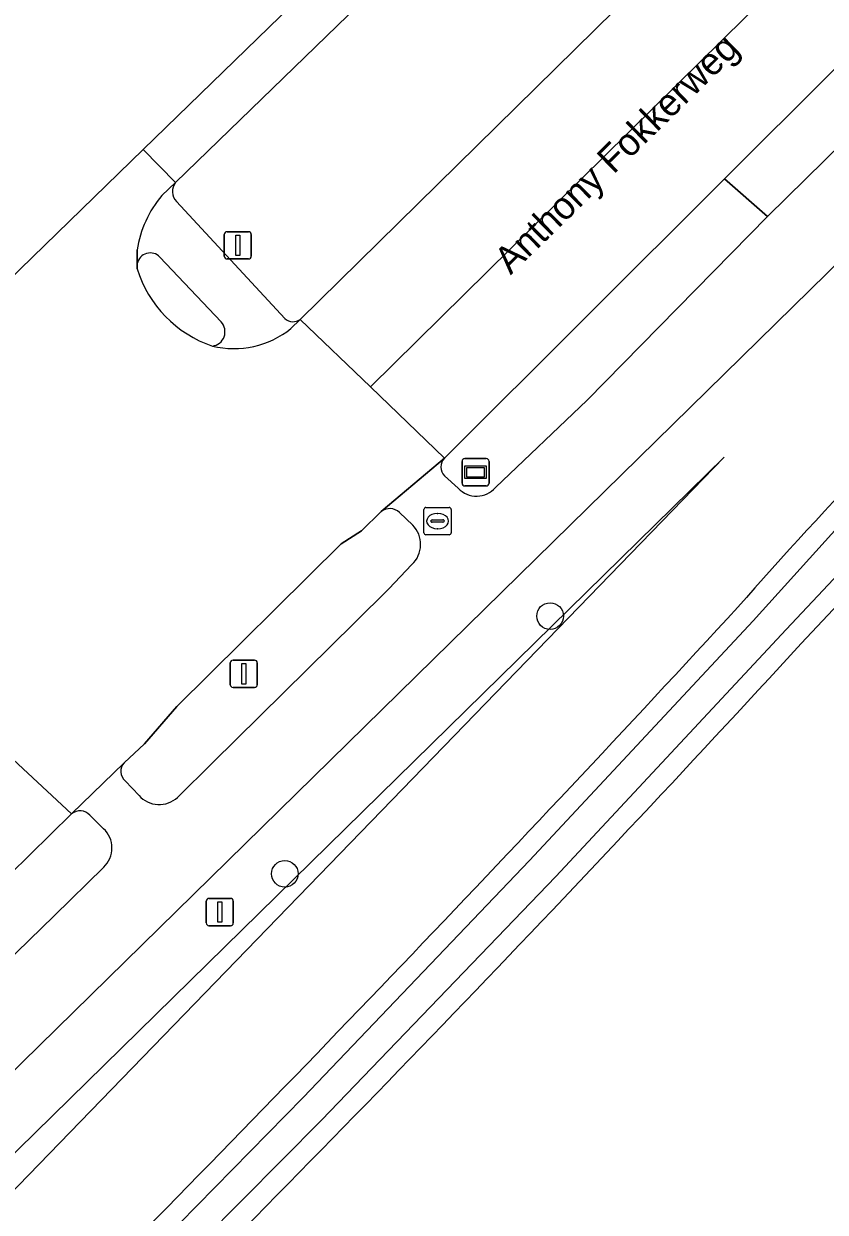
# Model space of a CAD drawing. Extents: x 156502 to 159075, y 384229 to 386100.
# Drawn here: x 156889.57 to 156918.98, y 385882.89 to 385926.49 of the extents above; entities that cross this region are included whole.
import ezdxf

# ---------------------------------------------------------------- set-up
doc = ezdxf.new("R2010")
doc.units = 0
for name, color, linetype in [('IMGEO_Berm_groen', 7, 'Continuous'), ('IMGEO_Boom', 7, 'Continuous'), ('IMGEO_Brandkraan', 7, 'Continuous'), ('IMGEO_Fietspad_gesloten', 7, 'Continuous'), ('IMGEO_Fietspad_open', 7, 'Continuous'), ('IMGEO_Groenvoorziening', 7, 'Continuous'), ('IMGEO_Lichtmast', 7, 'Continuous'), ('IMGEO_Loofbos', 7, 'Continuous'), ('IMGEO_Oever', 7, 'Continuous'), ('IMGEO_Openbare_ruimte_label', 7, 'Continuous'), ('IMGEO_Rijbaan_regionaal_gesloten', 7, 'Continuous'), ('IMGEO_Verkeersbordpaal', 7, 'Continuous'), ('IMGEO_Verkeerseiland_groen', 7, 'Continuous'), ('IMGEO_Verkeerseiland_open', 7, 'Continuous'), ('IMGEO_Verklikker', 7, 'Continuous'), ('IMGEO_Waterloop', 7, 'Continuous')]:
    doc.layers.add(name, color=color, linetype=linetype)

msp = doc.modelspace()

# ---------------------------------------------------------------- linework, layer by layer
at = {"layer": 'IMGEO_Berm_groen'}
msp.add_lwpolyline([(156943.436, 385945.532), (156945.978, 385947.733), (156944.931, 385949.532), (156941.12, 385946.235), (156931.18, 385936.654), (156915.286, 385920.806), (156916.861, 385919.427)], close=True, dxfattribs=at)
for points in [[(156916.861, 385919.427), (156915.286, 385920.806), (156905.009, 385910.559)], [(156906.88, 385909.479), (156910.242, 385912.682), (156916.861, 385919.427)], [(156905.007, 385909.901), (156905.515, 385909.453)], [(156891.327, 385897.504), (156890.556, 385896.744), (156880.841, 385887.205), (156882.39, 385885.7), (156890.686, 385893.756)], [(156892.499, 385896.958), (156891.994, 385897.455)], [(156890.686, 385893.756), (156892.502, 385895.546)]]:
    msp.add_lwpolyline(points, dxfattribs=at)
for centre, radius, start, end in [((156905.345, 385910.229), 0.471, 135.5045, 224.1472), ((156906.186, 385910.074), 0.914, 222.7938, 319.3887), ((156891.636, 385897.14), 0.477, 41.2701, 130.3268), ((156891.834, 385896.251), 0.971, 313.4602, 46.7832)]:
    msp.add_arc(centre, radius, start, end, dxfattribs=at)
at = {"layer": 'IMGEO_Boom'}
for centre in [(156908.883, 385904.761), (156899.148, 385895.304)]:
    msp.add_circle(centre, 0.489, dxfattribs=at)
at = {"layer": 'IMGEO_Brandkraan'}
for p, q in [((156904.254, 385907.821), (156904.254, 385908.673)), ((156904.329, 385908.747), (156905.181, 385908.747)), ((156904.742, 385908.527), (156904.767, 385908.527)), ((156905.255, 385908.673), (156905.255, 385907.821)), ((156904.513, 385908.241), (156904.513, 385908.253)), ((156904.951, 385908.204), (156904.553, 385908.204)), ((156904.556, 385908.29), (156904.954, 385908.29)), ((156904.765, 385907.967), (156904.74, 385907.967)), ((156904.997, 385908.253), (156904.997, 385908.241)), ((156905.181, 385907.747), (156904.329, 385907.747))]:
    msp.add_line(p, q, dxfattribs=at)
for points in [[(156904.254, 385907.821), (156904.254, 385908.673)], [(156904.329, 385908.747), (156905.181, 385908.747)], [(156905.255, 385908.673), (156905.255, 385907.821)], [(156905.181, 385907.747), (156904.329, 385907.747)]]:
    msp.add_lwpolyline(points, dxfattribs=at)
for centre, radius, start, end in [((156904.331, 385908.671), 0.0765, 91.552, 178.448), ((156904.331, 385908.671), 0.0765, 91.552, 178.448), ((156905.179, 385908.671), 0.0765, 1.552, 88.448), ((156905.179, 385908.671), 0.0765, 1.552, 88.448), ((156904.553, 385908.25), 0.0403, 85.8775, 175.7526), ((156904.55, 385908.24), 0.0366, 178.938, 274.7102), ((156904.954, 385908.247), 0.043, 264.8664, 352.4533), ((156904.958, 385908.252), 0.0386, 1.7309, 96.639), ((156904.331, 385907.823), 0.0765, 181.552, 268.448), ((156904.331, 385907.823), 0.0765, 181.552, 268.448), ((156905.179, 385907.823), 0.0765, 271.552, 358.448), ((156905.179, 385907.823), 0.0765, 271.552, 358.448)]:
    msp.add_arc(centre, radius, start, end, dxfattribs=at)
for centre, major_axis, ratio, start_param, end_param in [((156904.741, 385908.247), (-0.387, 0.002), 0.722429, 4.712389, 7.853982), ((156904.766, 385908.247), (-0.39, 0.002), 0.717154, 1.570796, 4.712389)]:
    msp.add_ellipse(centre, major_axis=major_axis, ratio=ratio, start_param=start_param, end_param=end_param, dxfattribs=at)
at = {"layer": 'IMGEO_Fietspad_gesloten'}
for points in [[(156873.791, 385872.985), (156944.187, 385942.001), (156947.572, 385944.991), (156947.985, 385945.377), (156946.393, 385948.094), (156945.978, 385947.733), (156943.436, 385945.532), (156916.861, 385919.427), (156910.242, 385912.682), (156906.88, 385909.479)], [(156905.009, 385910.559), (156902.688, 385908.6)], [(156905.515, 385909.453), (156905.007, 385909.901)], [(156903.357, 385908.566), (156903.843, 385908.097)], [(156903.815, 385906.653), (156902.968, 385905.759), (156901.719, 385904.522), (156896.499, 385899.38), (156895.214, 385898.109)], [(156893.251, 385899.377), (156891.327, 385897.504)], [(156893.799, 385898.18), (156893.291, 385898.71)], [(156891.994, 385897.455), (156892.499, 385896.958)], [(156892.502, 385895.546), (156890.686, 385893.756), (156882.39, 385885.7), (156878.321, 385881.75)]]:
    msp.add_lwpolyline(points, dxfattribs=at)
for centre, radius, start, end in [((156905.345, 385910.229), 0.471, 135.5045, 224.1472), ((156906.186, 385910.074), 0.914, 222.7938, 319.3887), ((156903.002, 385908.185), 0.52, 47.025, 127.1562), ((156903.124, 385907.389), 1.01, 313.2216, 44.5567), ((156893.595, 385899.063), 0.466, 137.595, 229.2689), ((156894.541, 385898.827), 0.984, 221.0993, 313.1557), ((156891.636, 385897.14), 0.477, 41.2701, 130.3268), ((156891.834, 385896.251), 0.971, 313.4602, 46.7832)]:
    msp.add_arc(centre, radius, start, end, dxfattribs=at)
at = {"layer": 'IMGEO_Fietspad_open'}
for points in [[(156895.139, 385920.67), (156894.641, 385920.187)], [(156899.156, 385915.676), (156895.173, 385919.975)], [(156893.736, 385918.196), (156893.734, 385917.699)], [(156894.565, 385917.933), (156896.811, 385915.552)], [(156899.374, 385915.313), (156899.709, 385915.643)]]:
    msp.add_lwpolyline(points, dxfattribs=at)
for centre, radius, start, end in [((156895.54, 385920.341), 0.518, 140.6271, 224.9744), ((156897.567, 385917.656), 3.869, 139.1392, 171.9728), ((156894.211, 385917.598), 0.488, 43.4644, 167.9888), ((156896.43, 385915.191), 0.525, 276.7087, 43.4086), ((156899.453, 385916.007), 0.445, 228.1121, 305.0578), ((156897.286, 385917.892), 3.318, 256.1428, 309.0031)]:
    msp.add_arc(centre, radius, start, end, dxfattribs=at)
at = {"layer": 'IMGEO_Groenvoorziening'}
msp.add_lwpolyline([(156845.546, 385840.494), (156871.07, 385864.986), (156915.271, 385910.594), (156887.455, 385883.327), (156885.077, 385880.811)], dxfattribs=at)
at = {"layer": 'IMGEO_Lichtmast'}
for p, q in [((156897.029, 385918.865), (156897.819, 385918.865)), ((156897.819, 385918.865), (156897.029, 385918.865)), ((156896.929, 385917.965), (156896.929, 385918.765)), ((156896.929, 385918.765), (156896.929, 385917.965)), ((156897.919, 385918.765), (156897.919, 385917.965)), ((156897.919, 385917.965), (156897.919, 385918.765)), ((156897.819, 385917.865), (156897.029, 385917.865)), ((156897.029, 385917.865), (156897.819, 385917.865)), ((156897.148, 385902.242), (156897.148, 385903.042)), ((156897.148, 385903.042), (156897.148, 385902.242)), ((156897.248, 385903.142), (156898.038, 385903.142)), ((156898.038, 385903.142), (156897.248, 385903.142)), ((156898.138, 385903.042), (156898.138, 385902.242)), ((156898.138, 385902.242), (156898.138, 385903.042)), ((156898.038, 385902.142), (156897.248, 385902.142)), ((156897.248, 385902.142), (156898.038, 385902.142))]:
    msp.add_line(p, q, dxfattribs=at)
for points in [[(156897.349, 385918.74), (156897.499, 385918.74), (156897.499, 385917.99), (156897.349, 385917.99), (156897.349, 385918.74)], [(156897.568, 385903.017), (156897.718, 385903.017), (156897.718, 385902.267), (156897.568, 385902.267), (156897.568, 385903.017)]]:
    msp.add_lwpolyline(points, dxfattribs=at)
for centre, start, end in [((156897.029, 385918.765), 90, 180), ((156897.029, 385918.765), 90, 180), ((156897.819, 385918.765), 0, 90), ((156897.819, 385918.765), 360, 90), ((156897.029, 385917.965), 180, 270), ((156897.029, 385917.965), 180, 270), ((156897.819, 385917.965), 270, 0), ((156897.819, 385917.965), 270, 0), ((156897.248, 385903.042), 90, 180), ((156897.248, 385903.042), 90, 180), ((156898.038, 385903.042), 0, 90), ((156898.038, 385903.042), 360, 90), ((156897.248, 385902.242), 180, 270), ((156897.248, 385902.242), 180, 270), ((156898.038, 385902.242), 270, 0), ((156898.038, 385902.242), 270, 0)]:
    msp.add_arc(centre, 0.1, start, end, dxfattribs=at)
at = {"layer": 'IMGEO_Loofbos'}
for points in [[(156939.905, 385930.087), (156949.647, 385941.356), (156947.572, 385944.991), (156944.187, 385942.001), (156873.791, 385872.985)], [(157027.141, 385797.89), (157015.854, 385829.061), (157010.805, 385836.629), (157000, 385855.161), (156976.182, 385896.012), (156952.047, 385938.123), (156945.972, 385932.521), (156939.53, 385926.107), (156933.24, 385919.544), (156932.218, 385920.282), (156927.135, 385915.226), (156928.076, 385914.361), (156918.102, 385903.758)], [(156885.077, 385880.811), (156887.455, 385883.327), (156915.271, 385910.594), (156871.07, 385864.986), (156845.546, 385840.494)]]:
    msp.add_lwpolyline(points, dxfattribs=at)
for centre, radius, start, end in [((157023.66, 385810.802), 143.279, 132.78404, 138.84683), ((156213.51, 386552.027), 954.833, 315.185311, 317.348363), ((156324.09, 386449.06), 806.353, 314.801867, 317.448151)]:
    msp.add_arc(centre, radius, start, end, dxfattribs=at)
at = {"layer": 'IMGEO_Oever'}
for points in [[(156918.102, 385903.758), (156928.076, 385914.361), (156927.135, 385915.226), (156926.339, 385915.957)], [(156927.002, 385914.322), (156917.548, 385904.272), (156909.091, 385895.2), (156900.494, 385886.259), (156891.761, 385877.452), (156868.007, 385854.16), (156858.229, 385844.972), (156848.315, 385835.931), (156838.268, 385827.039), (156835.089, 385824.285), (156831.899, 385821.544), (156828.697, 385818.817), (156821.36, 385812.649), (156813.965, 385806.55), (156806.514, 385800.519), (156797.646, 385793.521), (156788.691, 385786.634)], [(156791.706, 385789.946), (156801.678, 385797.68), (156811.506, 385805.594), (156821.188, 385813.688), (156830.418, 385821.329), (156839.492, 385829.155), (156848.406, 385837.163), (156857.206, 385845.158), (156865.872, 385853.299), (156874.402, 385861.582), (156891.394, 385878.511), (156899.818, 385887.098), (156908.134, 385895.789), (156916.339, 385904.585), (156919.557, 385908.145)]]:
    msp.add_lwpolyline(points, dxfattribs=at)
for centre, radius, start, end in [((157023.66, 385810.802), 143.279, 132.78404, 138.84683), ((156213.51, 386552.027), 954.833, 315.185311, 317.348363), ((156324.09, 386449.06), 806.353, 314.801867, 317.448151)]:
    msp.add_arc(centre, radius, start, end, dxfattribs=at)
at = {"layer": 'IMGEO_Rijbaan_regionaal_gesloten'}
for points in [[(156893.955, 385921.876), (156895.139, 385920.67), (156906.616, 385931.802), (156937.548, 385961.776), (156938.067, 385962.314), (156937.167, 385963.852)], [(156943.271, 385953.427), (156943.141, 385953.648), (156941.394, 385956.632), (156941.305, 385956.548), (156941.217, 385956.463), (156911.246, 385926.983), (156899.709, 385915.643), (156902.29, 385913.167), (156922.067, 385932.665)], [(156931.18, 385936.654), (156933.089, 385939.03), (156944.958, 385950.544), (156943.271, 385953.427), (156922.067, 385932.665), (156902.29, 385913.167), (156905.009, 385910.559), (156915.286, 385920.806)]]:
    msp.add_lwpolyline(points, close=True, dxfattribs=at)
for points in [[(156894.641, 385920.187), (156895.139, 385920.67), (156893.955, 385921.876), (156879.95, 385908.272)], [(156893.733, 385917.499), (156893.734, 385917.699), (156893.736, 385918.196)], [(156883.686, 385904.586), (156886.34, 385902.126), (156888.823, 385899.825), (156891.327, 385897.504), (156893.251, 385899.377), (156894.006, 385900.067), (156895.189, 385901.448), (156901.217, 385907.408), (156901.965, 385907.883), (156902.688, 385908.6), (156905.009, 385910.559), (156902.29, 385913.167), (156899.709, 385915.643), (156899.374, 385915.313)], [(156795.342, 385814.425), (156799.114, 385817.224), (156814.798, 385828.866), (156818.543, 385831.737), (156834.72, 385845.107), (156844.675, 385853.743), (156855.634, 385863.406), (156880.278, 385886.652), (156880.841, 385887.205), (156890.556, 385896.744), (156891.327, 385897.504), (156888.823, 385899.825), (156879.362, 385890.785), (156870.119, 385881.999), (156843.887, 385857.992), (156834.982, 385850.173), (156825.856, 385842.577), (156813.575, 385832.664), (156801.037, 385822.91), (156788.389, 385813.487)]]:
    msp.add_lwpolyline(points, dxfattribs=at)
for centre, radius, start, end in [((156897.567, 385917.656), 3.869, 139.1392, 171.9728), ((156897.884, 385918.787), 4.346, 197.2394, 251.3045), ((156897.286, 385917.892), 3.318, 256.1428, 309.0031)]:
    msp.add_arc(centre, radius, start, end, dxfattribs=at)
at = {"layer": 'IMGEO_Verkeersbordpaal'}
for p, q in [((156896.266, 385893.5), (156896.266, 385894.3)), ((156896.266, 385894.3), (156896.266, 385893.5)), ((156896.366, 385894.4), (156897.156, 385894.4)), ((156897.156, 385894.4), (156896.366, 385894.4)), ((156897.256, 385894.3), (156897.256, 385893.5)), ((156897.256, 385893.5), (156897.256, 385894.3)), ((156897.156, 385893.4), (156896.366, 385893.4)), ((156896.366, 385893.4), (156897.156, 385893.4))]:
    msp.add_line(p, q, dxfattribs=at)
msp.add_lwpolyline([(156896.686, 385894.275), (156896.836, 385894.275), (156896.836, 385893.525), (156896.686, 385893.525), (156896.686, 385894.275)], dxfattribs=at)
for centre, start, end in [((156896.366, 385894.3), 90, 180), ((156896.366, 385894.3), 90, 180), ((156897.156, 385894.3), 0, 90), ((156897.156, 385894.3), 360, 90), ((156896.366, 385893.5), 180, 270), ((156896.366, 385893.5), 180, 270), ((156897.156, 385893.5), 270, 0), ((156897.156, 385893.5), 270, 0)]:
    msp.add_arc(centre, 0.1, start, end, dxfattribs=at)
at = {"layer": 'IMGEO_Verkeerseiland_groen'}
for points in [[(156902.688, 385908.6), (156901.965, 385907.883), (156901.217, 385907.408), (156895.189, 385901.448), (156894.006, 385900.067), (156893.251, 385899.377)], [(156903.843, 385908.097), (156903.357, 385908.566)], [(156901.719, 385904.522), (156902.968, 385905.759), (156903.815, 385906.653)], [(156895.214, 385898.109), (156896.499, 385899.38), (156901.719, 385904.522)], [(156893.291, 385898.71), (156893.799, 385898.18)]]:
    msp.add_lwpolyline(points, dxfattribs=at)
for centre, radius, start, end in [((156903.002, 385908.185), 0.52, 47.025, 127.1562), ((156903.124, 385907.389), 1.01, 313.2216, 44.5567), ((156893.595, 385899.063), 0.466, 137.595, 229.2689), ((156894.541, 385898.827), 0.984, 221.0993, 313.1557)]:
    msp.add_arc(centre, radius, start, end, dxfattribs=at)
at = {"layer": 'IMGEO_Verkeerseiland_open'}
for points in [[(156899.709, 385915.643), (156911.246, 385926.983), (156906.616, 385931.802), (156895.139, 385920.67)], [(156895.173, 385919.975), (156899.156, 385915.676)], [(156893.734, 385917.699), (156893.733, 385917.499)], [(156896.811, 385915.552), (156894.565, 385917.933)]]:
    msp.add_lwpolyline(points, dxfattribs=at)
for centre, radius, start, end in [((156895.54, 385920.341), 0.518, 140.6271, 224.9744), ((156894.211, 385917.598), 0.488, 43.4644, 167.9888), ((156897.884, 385918.787), 4.346, 197.2394, 251.3045), ((156896.43, 385915.191), 0.525, 276.7087, 43.4086), ((156899.453, 385916.007), 0.445, 228.1121, 305.0578)]:
    msp.add_arc(centre, radius, start, end, dxfattribs=at)
at = {"layer": 'IMGEO_Verklikker'}
for p, q in [((156905.653, 385909.637), (156905.653, 385910.437)), ((156905.653, 385910.437), (156905.653, 385909.637)), ((156905.753, 385910.537), (156906.543, 385910.537)), ((156906.543, 385910.537), (156905.753, 385910.537)), ((156906.643, 385910.437), (156906.643, 385909.637)), ((156906.643, 385909.637), (156906.643, 385910.437)), ((156906.543, 385909.537), (156905.753, 385909.537)), ((156905.753, 385909.537), (156906.543, 385909.537))]:
    msp.add_line(p, q, dxfattribs=at)
for points in [[(156905.754, 385910.269), (156906.542, 385910.269), (156906.542, 385909.805), (156905.754, 385909.805), (156905.754, 385910.269)], [(156905.819, 385910.204), (156905.819, 385909.87), (156906.477, 385909.87), (156906.477, 385910.204), (156905.819, 385910.204)]]:
    msp.add_lwpolyline(points, dxfattribs=at)
for centre, start, end in [((156905.753, 385910.437), 90, 180), ((156905.753, 385910.437), 90, 180), ((156906.543, 385910.437), 0, 90), ((156906.543, 385910.437), 360, 90), ((156905.753, 385909.637), 180, 270), ((156905.753, 385909.637), 180, 270), ((156906.543, 385909.637), 270, 0), ((156906.543, 385909.637), 270, 0)]:
    msp.add_arc(centre, 0.1, start, end, dxfattribs=at)
at = {"layer": 'IMGEO_Waterloop'}
for points in [[(156788.691, 385786.634), (156797.646, 385793.521), (156806.514, 385800.519), (156813.965, 385806.55), (156821.36, 385812.649), (156828.697, 385818.817), (156831.899, 385821.544), (156835.089, 385824.285), (156838.268, 385827.039), (156848.315, 385835.931), (156858.229, 385844.972), (156868.007, 385854.16), (156891.761, 385877.452), (156900.494, 385886.259), (156909.091, 385895.2), (156917.548, 385904.272), (156927.002, 385914.322)], [(156919.557, 385908.145), (156916.339, 385904.585), (156908.134, 385895.789), (156899.818, 385887.098), (156891.394, 385878.511), (156874.402, 385861.582), (156865.872, 385853.299), (156857.206, 385845.158), (156848.406, 385837.163), (156839.492, 385829.155), (156830.418, 385821.329), (156821.188, 385813.688), (156811.506, 385805.594), (156801.678, 385797.68), (156791.706, 385789.946)]]:
    msp.add_lwpolyline(points, dxfattribs=at)

# ---------------------------------------------------------------- texts
at = {"layer": 'IMGEO_Openbare_ruimte_label'}
msp.add_text('Anthony Fokkerweg', height=1, rotation=44.3517, dxfattribs=at).set_placement((156907.437, 385917.256))

doc.saveas('drawing.dxf')
